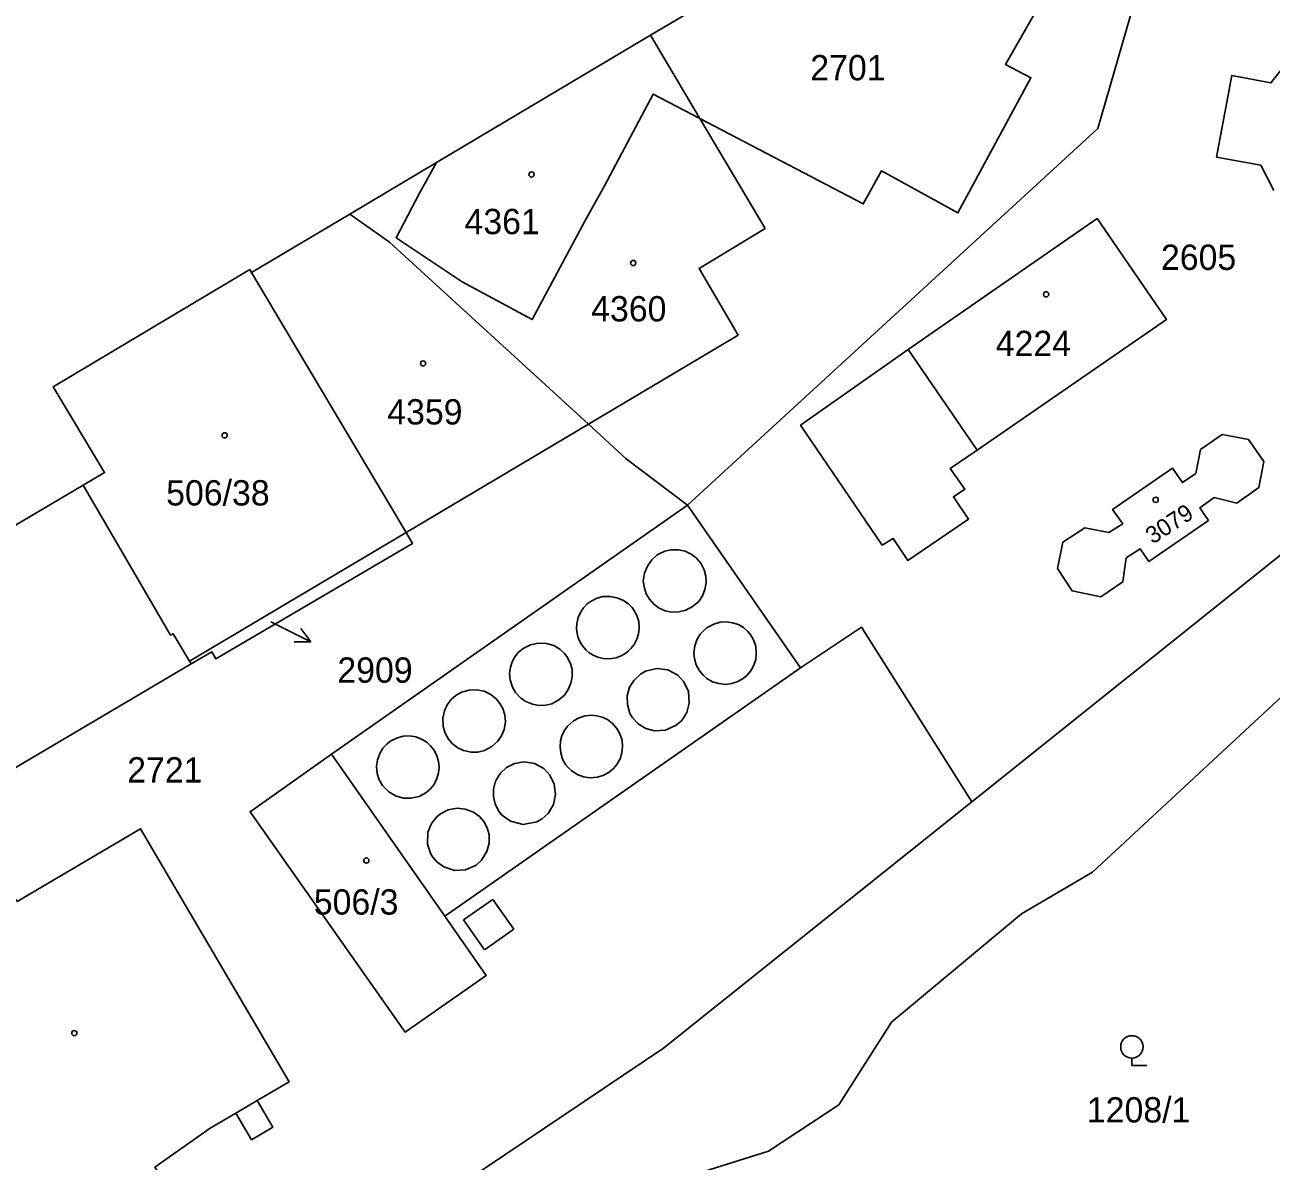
# Model space of a CAD drawing. Extents: x -679220 to -673243, y -1075091 to -1066557.
# Drawn here: x -676855.4 to -676771.7, y -1070747.8 to -1070671.5 of the extents above; entities that cross this region are included whole.
import ezdxf

# ---------------------------------------------------------------- set-up
doc = ezdxf.new("R2010")
doc.units = 0
for name, color, linetype in [('Hranice parcel', 7, 'Continuous'), ('Parcelní čísla', 7, 'Continuous'), ('Pop  PČ popisy', 7, 'Continuous'), ('Vnitřní kresba', 7, 'Continuous'), ('Značky budov', 7, 'Continuous'), ('Značky kultur', 7, 'Continuous')]:
    doc.layers.add(name, color=color, linetype=linetype)

msp = doc.modelspace()

# ---------------------------------------------------------------- linework, layer by layer
at = {"layer": 'Hranice parcel'}
for p, q in [((-676827.77, -1070680.74), (-676813.4, -1070672.19)), ((-676813.4, -1070672.19), (-676810.08, -1070677.78)), ((-676810.08, -1070677.78), (-676805.7, -1070685.17)), ((-676833.6, -1070684.2), (-676827.77, -1070680.74)), ((-676840.2, -1070688.13), (-676833.6, -1070684.2)), ((-676829.82, -1070705.59), (-676840.2, -1070688.13)), ((-676807.5, -1070692.33), (-676817.57, -1070698.31)), ((-676817.57, -1070698.31), (-676829.82, -1070705.59)), ((-676845.64, -1070712.47), (-676851.52, -1070702.41)), ((-676803.31, -1070714.66), (-676810.92, -1070703.75)), ((-676844.37, -1070714.23), (-676829.82, -1070705.59)), ((-676844.26, -1070714.41), (-676844.37, -1070714.23))]:
    msp.add_line(p, q, dxfattribs=at)
for points in [[(-676750.76, -1070636.36), (-676766.24, -1070631.36), (-676771.55, -1070637.63), (-676783.34, -1070678.45), (-676810.92, -1070703.75)], [(-676750.76, -1070636.36), (-676751.86, -1070641.87), (-676752.81, -1070646.73), (-676754.29, -1070657.14), (-676754.5, -1070658.58), (-676757.15, -1070682.42), (-676757.21, -1070682.95), (-676758.37, -1070689.69), (-676761.67, -1070698.83), (-676765.37, -1070703.02), (-676768.07, -1070705.38), (-676770.91, -1070706.97), (-676791.81, -1070723.66)], [(-676812.03, -1070662.23), (-676808.74, -1070663.96), (-676806.61, -1070659.93), (-676804.85, -1070660.87), (-676806.37, -1070663.74), (-676806.42, -1070663.85), (-676804.21, -1070665.02), (-676804.76, -1070666.06), (-676803.27, -1070666.91), (-676801.1, -1070662.84), (-676787.3, -1070670.23), (-676789.54, -1070674.15), (-676787.84, -1070675.05), (-676792.75, -1070684.12), (-676797.88, -1070681.3), (-676799.11, -1070683.52), (-676810.08, -1070677.78)], [(-676812.03, -1070662.23), (-676808.01, -1070668.99), (-676813.4, -1070672.19)], [(-676771.53, -1070682.62), (-676772.39, -1070680.92), (-676775.37, -1070680.39), (-676774.35, -1070674.9), (-676771.72, -1070675.39), (-676771, -1070674.49)], [(-676827.77, -1070680.74), (-676828.91, -1070682.79), (-676830.49, -1070685.79), (-676826.04, -1070688.75), (-676821.35, -1070691.29), (-676817.8, -1070684.67), (-676816.48, -1070682.3), (-676813.22, -1070676.14), (-676810.08, -1070677.78)], [(-676817.57, -1070698.31), (-676830.94, -1070686.08), (-676833.6, -1070684.2)], [(-676797.83, -1070706.44), (-676803.31, -1070698.38), (-676796.09, -1070693.29), (-676783.4, -1070684.5), (-676778.74, -1070691.29), (-676791.46, -1070700.06), (-676793.26, -1070701.28), (-676792.27, -1070702.68), (-676793.05, -1070703.18), (-676792.03, -1070704.68), (-676796.1, -1070707.47), (-676797.09, -1070705.98), (-676797.83, -1070706.44)], [(-676805.7, -1070685.17), (-676810.13, -1070687.85), (-676807.5, -1070692.33)], [(-676851.52, -1070702.41), (-676850.07, -1070701.56), (-676853.52, -1070695.8), (-676840.32, -1070687.92), (-676840.2, -1070688.13)], [(-676753.35, -1070693.05), (-676754.06, -1070696.49), (-676755.62, -1070699.7), (-676758.23, -1070703.29), (-676761.75, -1070707.57), (-676768.78, -1070714.55), (-676783.7, -1070728.39), (-676788.47, -1070731.18), (-676797.21, -1070738.47), (-676800.75, -1070744.01), (-676805.46, -1070747.13), (-676810.17, -1070748.61), (-676816.4, -1070753.01), (-676822.34, -1070756.86), (-676829.38, -1070760.64), (-676836.63, -1070765.94)], [(-676810.92, -1070703.75), (-676815.03, -1070700.63), (-676817.57, -1070698.31)], [(-676775.9, -1070704.78), (-676776.49, -1070703.92), (-676775.53, -1070703.23), (-676774, -1070703.61), (-676772.52, -1070702.57), (-676772.2, -1070700.81), (-676773.22, -1070699.33), (-676774.99, -1070699.01), (-676776.44, -1070700.01), (-676776.77, -1070701.62), (-676777.66, -1070702.23), (-676778.33, -1070701.26), (-676782.35, -1070704.03), (-676781.67, -1070705), (-676782.6, -1070705.58), (-676784.22, -1070705.28), (-676785.69, -1070706.24), (-676786.06, -1070708), (-676785.07, -1070709.51), (-676783.15, -1070709.91), (-676781.66, -1070708.9), (-676781.45, -1070707.29), (-676780.51, -1070706.67), (-676779.91, -1070707.54), (-676775.9, -1070704.78)], [(-676851.52, -1070702.41), (-676885.18, -1070722.27), (-676884.94, -1070722.68), (-676878.23, -1070734.06)], [(-676810.92, -1070703.75), (-676834.83, -1070720.46), (-676840.3, -1070724.33), (-676829.87, -1070739.14), (-676824.43, -1070735.34), (-676827.22, -1070731.34), (-676803.31, -1070714.66)], [(-676829.82, -1070705.59), (-676829.39, -1070706.31), (-676842.59, -1070714.07), (-676842.87, -1070713.59), (-676844.26, -1070714.41)], [(-676803.31, -1070714.66), (-676799.22, -1070711.94), (-676795.53, -1070717.78), (-676791.81, -1070723.66)], [(-676844.37, -1070714.23), (-676845.46, -1070712.39), (-676845.64, -1070712.47)], [(-676844.26, -1070714.41), (-676878.06, -1070734.35), (-676878.23, -1070734.06)], [(-676791.81, -1070723.66), (-676812.53, -1070740.21), (-676828.51, -1070750.96), (-676857.49, -1070772.45), (-676885.64, -1070779.16)], [(-676877.98, -1070745.56), (-676867.53, -1070738.15), (-676856.14, -1070730.08), (-676855.94, -1070730.37), (-676847.66, -1070725.47), (-676837.67, -1070742.46), (-676839.83, -1070743.73), (-676838.77, -1070745.52), (-676840.2, -1070746.36), (-676841.25, -1070744.57), (-676842.99, -1070745.59), (-676846.69, -1070748.21), (-676845.57, -1070749.9), (-676846.66, -1070750.67), (-676847.85, -1070749.03), (-676852.87, -1070752.58), (-676851.87, -1070754), (-676863.38, -1070762.15), (-676864.51, -1070760.55), (-676868.75, -1070763.56), (-676867.04, -1070765.97), (-676885.64, -1070779.16)]]:
    msp.add_lwpolyline(points, dxfattribs=at)
at = {"layer": 'Pop  PČ popisy'}
for p, q in [((-676838.9, -1070711.57), (-676836.226, -1070712.932)), ((-676836.226, -1070712.932), (-676836.891, -1070712.032)), ((-676836.226, -1070712.932), (-676837.346, -1070712.924))]:
    msp.add_line(p, q, dxfattribs=at)
at = {"layer": 'Vnitřní kresba'}
for p, q in [((-676791.46, -1070700.06), (-676796.09, -1070693.29)), ((-676812.97, -1070707.11), (-676813.31, -1070707.42)), ((-676812.82, -1070707.01), (-676812.97, -1070707.11)), ((-676812.44, -1070706.84), (-676812.82, -1070707.01)), ((-676812.03, -1070706.74), (-676812.44, -1070706.84)), ((-676811.52, -1070706.74), (-676812.03, -1070706.74)), ((-676811.07, -1070706.84), (-676811.52, -1070706.74)), ((-676810.67, -1070707.03), (-676811.07, -1070706.84)), ((-676810.34, -1070707.28), (-676810.67, -1070707.03)), ((-676813.61, -1070707.84), (-676813.79, -1070708.32)), ((-676813.31, -1070707.42), (-676813.61, -1070707.84)), ((-676810.02, -1070707.65), (-676810.34, -1070707.28)), ((-676809.8, -1070708.08), (-676810.02, -1070707.65)), ((-676809.68, -1070708.52), (-676809.8, -1070708.08)), ((-676813.79, -1070708.32), (-676813.88, -1070708.85)), ((-676813.88, -1070708.85), (-676813.81, -1070709.32)), ((-676809.66, -1070708.97), (-676809.68, -1070708.52)), ((-676813.81, -1070709.32), (-676813.68, -1070709.69)), ((-676813.68, -1070709.69), (-676813.47, -1070710.06)), ((-676809.91, -1070709.83), (-676809.74, -1070709.41)), ((-676809.74, -1070709.41), (-676809.66, -1070708.97)), ((-676817.9, -1070710.63), (-676817.65, -1070710.38)), ((-676817.65, -1070710.38), (-676817.46, -1070710.24)), ((-676817.46, -1070710.24), (-676817.05, -1070710.01)), ((-676817.05, -1070710.01), (-676816.6, -1070709.89)), ((-676816.6, -1070709.89), (-676816.11, -1070709.87)), ((-676816.11, -1070709.87), (-676815.65, -1070709.96)), ((-676815.65, -1070709.96), (-676815.26, -1070710.12)), ((-676815.26, -1070710.12), (-676814.88, -1070710.37)), ((-676814.88, -1070710.37), (-676814.64, -1070710.62)), ((-676814.64, -1070710.62), (-676814.52, -1070710.79)), ((-676813.47, -1070710.06), (-676813.18, -1070710.4)), ((-676813.18, -1070710.4), (-676812.82, -1070710.66)), ((-676811.02, -1070710.8), (-676810.57, -1070710.55)), ((-676810.57, -1070710.55), (-676810.16, -1070710.21)), ((-676810.16, -1070710.21), (-676809.91, -1070709.83)), ((-676818.35, -1070711.71), (-676818.25, -1070711.29)), ((-676818.25, -1070711.29), (-676818.1, -1070710.95)), ((-676818.1, -1070710.95), (-676817.9, -1070710.63)), ((-676814.52, -1070710.79), (-676814.32, -1070711.16)), ((-676814.32, -1070711.16), (-676814.19, -1070711.56)), ((-676812.82, -1070710.66), (-676812.41, -1070710.84)), ((-676812.41, -1070710.84), (-676811.98, -1070710.93)), ((-676811.98, -1070710.93), (-676811.49, -1070710.92)), ((-676811.49, -1070710.92), (-676811.02, -1070710.8)), ((-676818.36, -1070712.04), (-676818.35, -1070711.71)), ((-676818.32, -1070712.37), (-676818.36, -1070712.04)), ((-676814.16, -1070711.99), (-676814.2, -1070712.38)), ((-676814.19, -1070711.56), (-676814.16, -1070711.99)), ((-676810.06, -1070712.42), (-676809.82, -1070712.16)), ((-676809.82, -1070712.16), (-676809.58, -1070711.96)), ((-676809.58, -1070711.96), (-676809.15, -1070711.74)), ((-676809.15, -1070711.74), (-676808.71, -1070711.61)), ((-676808.71, -1070711.61), (-676808.31, -1070711.58)), ((-676808.31, -1070711.58), (-676807.9, -1070711.64)), ((-676807.9, -1070711.64), (-676807.49, -1070711.77)), ((-676807.49, -1070711.77), (-676807.16, -1070711.97)), ((-676807.16, -1070711.97), (-676806.86, -1070712.22)), ((-676806.86, -1070712.22), (-676806.66, -1070712.47)), ((-676821.96, -1070713.38), (-676821.47, -1070713.13)), ((-676821.47, -1070713.13), (-676820.94, -1070713.01)), ((-676820.94, -1070713.01), (-676820.39, -1070713.03)), ((-676820.39, -1070713.03), (-676819.9, -1070713.17)), ((-676818.25, -1070712.65), (-676818.32, -1070712.37)), ((-676818.12, -1070712.95), (-676818.25, -1070712.65)), ((-676817.97, -1070713.19), (-676818.12, -1070712.95)), ((-676814.49, -1070713.11), (-676814.71, -1070713.37)), ((-676814.31, -1070712.75), (-676814.49, -1070713.11)), ((-676814.2, -1070712.38), (-676814.31, -1070712.75)), ((-676810.43, -1070713.19), (-676810.28, -1070712.79)), ((-676810.28, -1070712.79), (-676810.06, -1070712.42)), ((-676806.66, -1070712.47), (-676806.48, -1070712.78)), ((-676806.48, -1070712.78), (-676806.33, -1070713.22)), ((-676822.69, -1070714.27), (-676822.51, -1070713.94)), ((-676822.51, -1070713.94), (-676822.28, -1070713.65)), ((-676822.28, -1070713.65), (-676821.96, -1070713.38)), ((-676819.9, -1070713.17), (-676819.49, -1070713.41)), ((-676819.49, -1070713.41), (-676819.18, -1070713.7)), ((-676819.18, -1070713.7), (-676819.01, -1070713.92)), ((-676819.01, -1070713.92), (-676818.79, -1070714.34)), ((-676817.72, -1070713.48), (-676817.97, -1070713.19)), ((-676817.51, -1070713.66), (-676817.72, -1070713.48)), ((-676817.25, -1070713.82), (-676817.51, -1070713.66)), ((-676816.93, -1070713.96), (-676817.25, -1070713.82)), ((-676816.57, -1070714.04), (-676816.93, -1070713.96)), ((-676815.37, -1070713.87), (-676815.71, -1070713.99)), ((-676815.06, -1070713.68), (-676815.37, -1070713.87)), ((-676814.9, -1070713.56), (-676815.06, -1070713.68)), ((-676814.71, -1070713.37), (-676814.9, -1070713.56)), ((-676810.48, -1070713.66), (-676810.43, -1070713.19)), ((-676810.44, -1070714.06), (-676810.48, -1070713.66)), ((-676806.33, -1070713.22), (-676806.29, -1070713.67)), ((-676806.29, -1070713.67), (-676806.33, -1070714.11)), ((-676822.86, -1070715.06), (-676822.8, -1070714.63)), ((-676822.8, -1070714.63), (-676822.69, -1070714.27)), ((-676818.79, -1070714.34), (-676818.67, -1070714.76)), ((-676818.67, -1070714.76), (-676818.66, -1070715.27)), ((-676816.18, -1070714.06), (-676816.57, -1070714.04)), ((-676815.71, -1070713.99), (-676816.18, -1070714.06)), ((-676813.74, -1070714.9), (-676812.98, -1070714.72)), ((-676812.98, -1070714.72), (-676812.24, -1070714.81)), ((-676810.34, -1070714.47), (-676810.44, -1070714.06)), ((-676810.11, -1070714.88), (-676810.34, -1070714.47)), ((-676806.45, -1070714.5), (-676806.66, -1070714.87)), ((-676806.33, -1070714.11), (-676806.45, -1070714.5)), ((-676822.82, -1070715.48), (-676822.86, -1070715.06)), ((-676822.68, -1070715.96), (-676822.82, -1070715.48)), ((-676818.66, -1070715.27), (-676818.74, -1070715.71)), ((-676814.5, -1070715.49), (-676814.8, -1070715.96)), ((-676814.08, -1070715.1), (-676814.5, -1070715.49)), ((-676814.08, -1070715.1), (-676813.74, -1070714.9)), ((-676811.56, -1070715.17), (-676812.24, -1070714.81)), ((-676811.15, -1070715.61), (-676811.56, -1070715.17)), ((-676810.85, -1070716.25), (-676811.15, -1070715.61)), ((-676809.87, -1070715.17), (-676810.11, -1070714.88)), ((-676809.61, -1070715.39), (-676809.87, -1070715.17)), ((-676809.24, -1070715.61), (-676809.61, -1070715.39)), ((-676808.8, -1070715.73), (-676809.24, -1070715.61)), ((-676807.53, -1070715.59), (-676807.94, -1070715.73)), ((-676807.18, -1070715.39), (-676807.53, -1070715.59)), ((-676806.93, -1070715.18), (-676807.18, -1070715.39)), ((-676806.66, -1070714.87), (-676806.93, -1070715.18)), ((-676826.45, -1070716.51), (-676826.07, -1070716.3)), ((-676826.07, -1070716.3), (-676825.61, -1070716.17)), ((-676825.61, -1070716.17), (-676825.09, -1070716.14)), ((-676825.09, -1070716.14), (-676824.57, -1070716.24)), ((-676824.57, -1070716.24), (-676824.12, -1070716.46)), ((-676824.12, -1070716.46), (-676823.77, -1070716.76)), ((-676822.46, -1070716.33), (-676822.68, -1070715.96)), ((-676822.12, -1070716.7), (-676822.46, -1070716.33)), ((-676818.93, -1070716.13), (-676819.18, -1070716.5)), ((-676818.74, -1070715.71), (-676818.93, -1070716.13)), ((-676814.8, -1070715.96), (-676814.96, -1070716.55)), ((-676810.79, -1070717.04), (-676810.85, -1070716.25)), ((-676808.36, -1070715.78), (-676808.8, -1070715.73)), ((-676807.94, -1070715.73), (-676808.36, -1070715.78)), ((-676827.24, -1070717.55), (-676827.06, -1070717.15)), ((-676827.06, -1070717.15), (-676826.79, -1070716.8)), ((-676826.79, -1070716.8), (-676826.45, -1070716.51)), ((-676823.77, -1070716.76), (-676823.51, -1070717.06)), ((-676823.51, -1070717.06), (-676823.31, -1070717.41)), ((-676821.77, -1070716.94), (-676822.12, -1070716.7)), ((-676821.33, -1070717.12), (-676821.77, -1070716.94)), ((-676820.87, -1070717.2), (-676821.33, -1070717.12)), ((-676820.42, -1070717.17), (-676820.87, -1070717.2)), ((-676820.03, -1070717.08), (-676820.42, -1070717.17)), ((-676819.56, -1070716.82), (-676820.03, -1070717.08)), ((-676819.18, -1070716.5), (-676819.56, -1070716.82)), ((-676814.96, -1070716.55), (-676814.95, -1070717.14)), ((-676814.95, -1070717.14), (-676814.78, -1070717.73)), ((-676810.96, -1070717.67), (-676810.79, -1070717.04)), ((-676827.35, -1070718.05), (-676827.24, -1070717.55)), ((-676827.32, -1070718.6), (-676827.35, -1070718.05)), ((-676823.31, -1070717.41), (-676823.19, -1070717.82)), ((-676823.19, -1070717.82), (-676823.14, -1070718.3)), ((-676818.57, -1070718.23), (-676818.2, -1070718.03)), ((-676818.2, -1070718.03), (-676817.79, -1070717.89)), ((-676817.79, -1070717.89), (-676817.37, -1070717.85)), ((-676817.37, -1070717.85), (-676817.01, -1070717.89)), ((-676817.01, -1070717.89), (-676816.65, -1070717.98)), ((-676816.65, -1070717.98), (-676816.29, -1070718.15)), ((-676816.29, -1070718.15), (-676815.95, -1070718.4)), ((-676814.6, -1070718.02), (-676814.78, -1070717.73)), ((-676814.6, -1070718.02), (-676814.23, -1070718.43)), ((-676811.29, -1070718.2), (-676810.96, -1070717.67)), ((-676827.19, -1070719.06), (-676827.32, -1070718.6)), ((-676823.22, -1070718.8), (-676823.4, -1070719.24)), ((-676823.14, -1070718.3), (-676823.22, -1070718.8)), ((-676819.35, -1070719.23), (-676819.2, -1070718.91)), ((-676819.2, -1070718.91), (-676818.98, -1070718.58)), ((-676818.98, -1070718.58), (-676818.57, -1070718.23)), ((-676815.95, -1070718.4), (-676815.65, -1070718.75)), ((-676815.65, -1070718.75), (-676815.45, -1070719.11)), ((-676814.23, -1070718.43), (-676813.71, -1070718.75)), ((-676813.71, -1070718.75), (-676813.13, -1070718.9)), ((-676813.13, -1070718.9), (-676812.38, -1070718.86)), ((-676812.38, -1070718.86), (-676811.68, -1070718.53)), ((-676811.29, -1070718.2), (-676811.68, -1070718.53)), ((-676831.38, -1070720.06), (-676831.1, -1070719.78)), ((-676831.1, -1070719.78), (-676830.9, -1070719.62)), ((-676830.9, -1070719.62), (-676830.47, -1070719.39)), ((-676830.47, -1070719.39), (-676830.02, -1070719.26)), ((-676830.02, -1070719.26), (-676829.58, -1070719.24)), ((-676829.58, -1070719.24), (-676829.16, -1070719.31)), ((-676829.16, -1070719.31), (-676828.78, -1070719.46)), ((-676828.78, -1070719.46), (-676828.43, -1070719.67)), ((-676828.43, -1070719.67), (-676828.17, -1070719.9)), ((-676826.96, -1070719.47), (-676827.19, -1070719.06)), ((-676826.69, -1070719.77), (-676826.96, -1070719.47)), ((-676826.34, -1070720.05), (-676826.69, -1070719.77)), ((-676823.67, -1070719.61), (-676824.05, -1070719.96)), ((-676823.4, -1070719.24), (-676823.67, -1070719.61)), ((-676819.47, -1070719.99), (-676819.45, -1070719.58)), ((-676819.45, -1070719.58), (-676819.35, -1070719.23)), ((-676815.45, -1070719.11), (-676815.31, -1070719.52)), ((-676815.31, -1070719.52), (-676815.27, -1070719.95)), ((-676834.83, -1070720.46), (-676827.22, -1070731.34)), ((-676831.74, -1070720.84), (-676831.59, -1070720.43)), ((-676831.59, -1070720.43), (-676831.38, -1070720.06)), ((-676828.17, -1070719.9), (-676827.96, -1070720.17)), ((-676827.96, -1070720.17), (-676827.75, -1070720.55)), ((-676827.75, -1070720.55), (-676827.64, -1070720.95)), ((-676825.95, -1070720.23), (-676826.34, -1070720.05)), ((-676825.45, -1070720.33), (-676825.95, -1070720.23)), ((-676824.99, -1070720.33), (-676825.45, -1070720.33)), ((-676824.54, -1070720.22), (-676824.99, -1070720.33)), ((-676824.05, -1070719.96), (-676824.54, -1070720.22)), ((-676819.43, -1070720.38), (-676819.47, -1070719.99)), ((-676819.31, -1070720.8), (-676819.43, -1070720.38)), ((-676815.32, -1070720.38), (-676815.43, -1070720.77)), ((-676815.27, -1070719.95), (-676815.32, -1070720.38)), ((-676831.8, -1070721.29), (-676831.74, -1070720.84)), ((-676831.75, -1070721.76), (-676831.8, -1070721.29)), ((-676827.64, -1070720.95), (-676827.6, -1070721.33)), ((-676827.6, -1070721.33), (-676827.64, -1070721.73)), ((-676823.47, -1070721.74), (-676823.07, -1070721.37)), ((-676823.07, -1070721.37), (-676822.53, -1070721.1)), ((-676822.53, -1070721.1), (-676821.88, -1070720.99)), ((-676821.88, -1070720.99), (-676821.18, -1070721.1)), ((-676821.18, -1070721.1), (-676820.56, -1070721.43)), ((-676820.56, -1070721.43), (-676820.15, -1070721.88)), ((-676819.1, -1070721.15), (-676819.31, -1070720.8)), ((-676818.93, -1070721.37), (-676819.1, -1070721.15)), ((-676818.69, -1070721.59), (-676818.93, -1070721.37)), ((-676815.89, -1070721.43), (-676816.18, -1070721.67)), ((-676815.66, -1070721.16), (-676815.89, -1070721.43)), ((-676815.43, -1070720.77), (-676815.66, -1070721.16)), ((-676831.62, -1070722.18), (-676831.75, -1070721.76)), ((-676831.4, -1070722.56), (-676831.62, -1070722.18)), ((-676827.75, -1070722.11), (-676827.94, -1070722.5)), ((-676827.64, -1070721.73), (-676827.75, -1070722.11)), ((-676823.94, -1070722.82), (-676823.81, -1070722.29)), ((-676823.81, -1070722.29), (-676823.47, -1070721.74)), ((-676820.15, -1070721.88), (-676819.86, -1070722.48)), ((-676818.33, -1070721.83), (-676818.69, -1070721.59)), ((-676817.9, -1070721.99), (-676818.33, -1070721.83)), ((-676817.44, -1070722.06), (-676817.9, -1070721.99)), ((-676816.95, -1070722.01), (-676817.44, -1070722.06)), ((-676816.54, -1070721.88), (-676816.95, -1070722.01)), ((-676816.18, -1070721.67), (-676816.54, -1070721.88)), ((-676830.98, -1070723), (-676831.4, -1070722.56)), ((-676830.53, -1070723.26), (-676830.98, -1070723)), ((-676828.5, -1070723.06), (-676828.95, -1070723.3)), ((-676828.2, -1070722.81), (-676828.5, -1070723.06)), ((-676827.94, -1070722.5), (-676828.2, -1070722.81)), ((-676823.95, -1070723.32), (-676823.94, -1070722.82)), ((-676819.78, -1070723.15), (-676819.92, -1070723.85)), ((-676819.86, -1070722.48), (-676819.78, -1070723.15)), ((-676830, -1070723.42), (-676830.53, -1070723.26)), ((-676829.5, -1070723.43), (-676830, -1070723.42)), ((-676828.95, -1070723.3), (-676829.5, -1070723.43)), ((-676823.83, -1070723.82), (-676823.95, -1070723.32)), ((-676823.59, -1070724.29), (-676823.83, -1070723.82)), ((-676819.92, -1070723.85), (-676820.28, -1070724.45)), ((-676828.12, -1070725.12), (-676827.76, -1070724.67)), ((-676827.76, -1070724.67), (-676827.51, -1070724.47)), ((-676827.51, -1070724.47), (-676826.98, -1070724.2)), ((-676826.98, -1070724.2), (-676826.38, -1070724.09)), ((-676826.38, -1070724.09), (-676825.84, -1070724.15)), ((-676825.84, -1070724.15), (-676825.29, -1070724.36)), ((-676825.29, -1070724.36), (-676824.89, -1070724.66)), ((-676824.89, -1070724.66), (-676824.6, -1070724.99)), ((-676823.4, -1070724.53), (-676823.59, -1070724.29)), ((-676823.4, -1070724.53), (-676822.8, -1070724.96)), ((-676820.67, -1070724.8), (-676821.03, -1070725.01)), ((-676820.28, -1070724.45), (-676820.67, -1070724.8)), ((-676828.35, -1070725.7), (-676828.12, -1070725.12)), ((-676824.6, -1070724.99), (-676824.37, -1070725.41)), ((-676824.37, -1070725.41), (-676824.24, -1070725.86)), ((-676822.8, -1070724.96), (-676821.96, -1070725.19)), ((-676821.96, -1070725.19), (-676821.03, -1070725.01)), ((-676828.39, -1070726.52), (-676828.35, -1070725.7)), ((-676828.16, -1070727.19), (-676828.39, -1070726.52)), ((-676824.23, -1070726.45), (-676824.39, -1070727.01)), ((-676824.24, -1070725.86), (-676824.23, -1070726.45)), ((-676828.03, -1070727.39), (-676828.16, -1070727.19)), ((-676824.39, -1070727.01), (-676824.76, -1070727.59)), ((-676827.75, -1070727.7), (-676828.03, -1070727.39)), ((-676827.29, -1070728.04), (-676827.75, -1070727.7)), ((-676826.54, -1070728.27), (-676827.29, -1070728.04)), ((-676825.12, -1070727.91), (-676825.82, -1070728.23)), ((-676824.76, -1070727.59), (-676825.12, -1070727.91)), ((-676825.82, -1070728.23), (-676826.54, -1070728.27)), ((-676825.95, -1070731.59), (-676823.98, -1070730.22)), ((-676823.98, -1070730.22), (-676822.58, -1070732.22)), ((-676824.55, -1070733.6), (-676825.95, -1070731.59)), ((-676822.58, -1070732.22), (-676824.55, -1070733.6)), ((-676839.83, -1070743.73), (-676841.25, -1070744.57))]:
    msp.add_line(p, q, dxfattribs=at)
at = {"layer": 'Značky budov'}
for centre in [(-676821.387, -1070681.539), (-676814.557, -1070687.489), (-676786.817, -1070689.589), (-676828.677, -1070694.229), (-676842.007, -1070699.059), (-676779.457, -1070703.389), (-676832.487, -1070727.609), (-676852.107, -1070739.199)]:
    msp.add_circle(centre, 0.175, dxfattribs=at)
at = {"layer": 'Značky kultur'}
for p, q in [((-676781.06, -1070740.872), (-676781.06, -1070741.37)), ((-676781.06, -1070741.37), (-676780.059, -1070741.37))]:
    msp.add_line(p, q, dxfattribs=at)
msp.add_circle((-676781.059, -1070740.121), 0.75, dxfattribs=at)

# ---------------------------------------------------------------- texts
at = {"layer": 'Parcelní čísla'}
for s, p in [('2701', (-676802.664, -1070675.22)), ('4361', (-676825.894, -1070685.55)), ('2605', (-676779.104, -1070687.95)), ('4360', (-676817.384, -1070691.41)), ('4224', (-676790.204, -1070693.739)), ('4359', (-676831.084, -1070698.33)), ('506/38', (-676845.937, -1070703.769)), ('2909', (-676834.434, -1070715.67)), ('2721', (-676848.554, -1070722.37)), ('506/3', (-676836.018, -1070731.239)), ('1208/1', (-676784.08, -1070745.2))]:
    msp.add_text(s, height=1.7, dxfattribs=at).set_placement(p)
msp.add_text('3079', height=1.14, rotation=33, dxfattribs=at).set_placement((-676779.659, -1070706.398))

doc.saveas('drawing.dxf')
